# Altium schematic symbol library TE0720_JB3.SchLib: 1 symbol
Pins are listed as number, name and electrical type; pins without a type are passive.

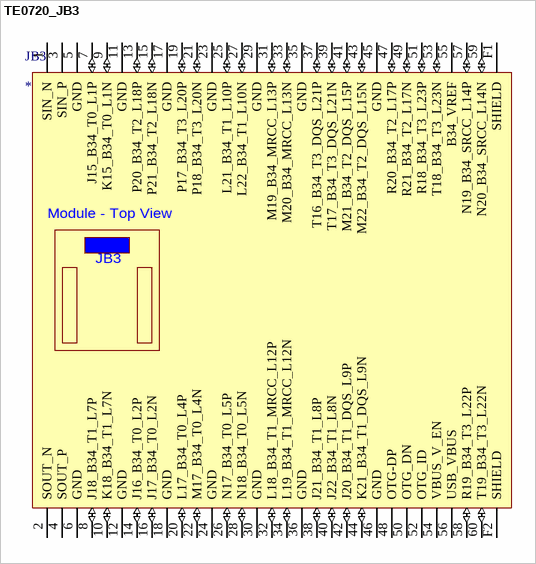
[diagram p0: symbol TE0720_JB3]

## TE0720_JB3
designator JB3
pins: 1 SIN_N (power), 2 SOUT_N, 3 SIN_P (power), 4 SOUT_P, 5 GND (power), 6 GND (power), 7 J15_B34_T0_L1P (io), 8 J18_B34_T1_L7P (io), 9 K15_B34_T0_L1N (io), 10 K18_B34_T1_L7N (io), 11 GND (power), 12 GND (power), 13 P20_B34_T2_L18P (io), 14 J16_B34_T0_L2P (io), 15 P21_B34_T2_L18N (io), 16 J17_B34_T0_L2N (io), 17 GND (power), 18 GND (power), 19 P17_B34_T3_L20P (io), 20 L17_B34_T0_L4P (io), 21 P18_B34_T3_L20N (io), 22 M17_B34_T0_L4N (io), 23 GND (power), 24 GND (power), 25 L21_B34_T1_L10P (io), 26 N17_B34_T0_L5P (io), 27 L22_B34_T1_L10N (io), 28 N18_B34_T0_L5N (io), 29 GND (power), 30 GND (power), 31 M19_B34_MRCC_L13P (io), 32 L18_B34_T1_MRCC_L12P (io), 33 M20_B34_MRCC_L13N (io), 34 L19_B34_T1_MRCC_L12N (io), 35 GND (power), 36 GND (power), 37 T16_B34_T3_DQS_L21P (io), 38 J21_B34_T1_L8P (io), 39 T17_B34_T3_DQS_L21N (io), 40 J22_B34_T1_L8N (io), 41 M21_B34_T2_DQS_L15P (io), 42 J20_B34_T1_DQS_L9P (io), 43 M22_B34_T2_DQS_L15N (io), 44 K21_B34_T1_DQS_L9N (io), 45 GND (power), 46 GND (power), 47 R20_B34_T2_L17P (io), 48 OTG-DP (power), 49 R21_B34_T2_L17N (io), 50 OTG_DN (power), 51 R18_B34_T3_L23P (io), 52 OTG_ID (power), 53 T18_B34_T3_L23N (io), 54 VBUS_V_EN (power), 55 B34_VREF (power), 56 USB_VBUS (power), 57 N19_B34_SRCC_L14P (io), 58 R19_B34_T3_L22P (io), 59 N20_B34_SRCC_L14N (io), 60 T19_B34_T3_L22N (io), F1 SHIELD (power), F2 SHIELD (power)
